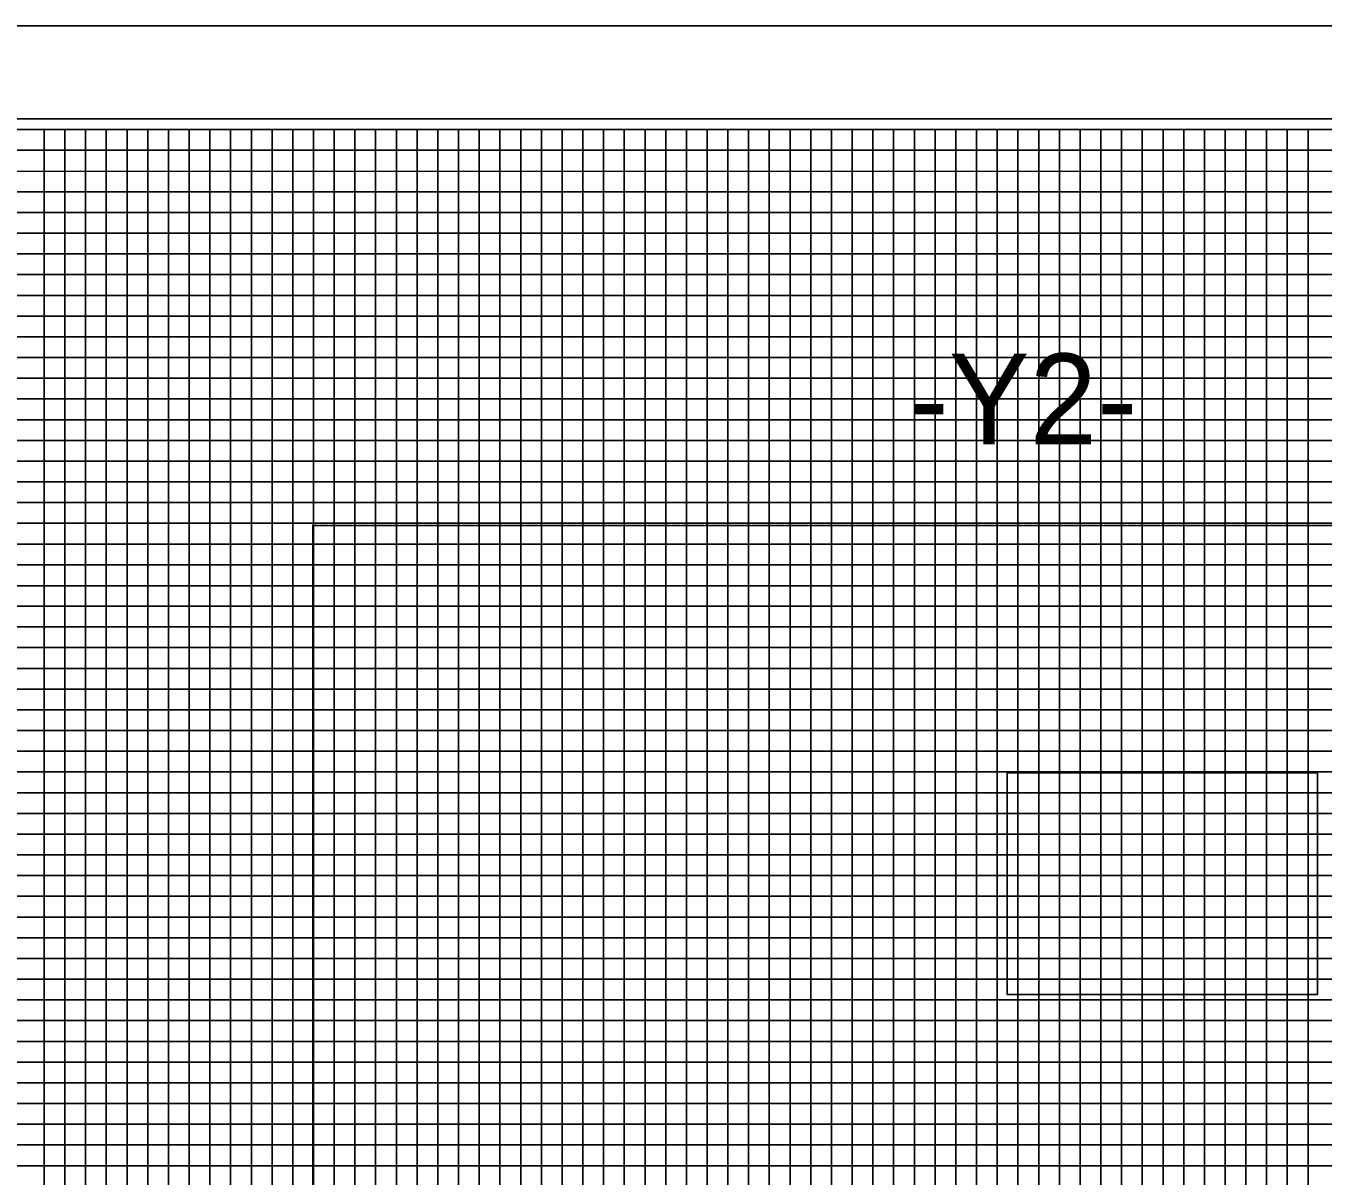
# Model space of a CAD drawing. Extents: x 1624665 to 1626605, y 896887 to 897987.
# Drawn here: x 1625613 to 1625926, y 897709.9 to 897987.4 of the extents above; entities that cross this region are included whole.
import ezdxf

# ---------------------------------------------------------------- set-up
doc = ezdxf.new("R2010")
doc.units = 0
for name, color, linetype in [('Prop DSN Text', 7, 'Continuous'), ('Prop PHM Black Shape', 7, 'Continuous'), ('Scratch_Level_1', 7, 'Continuous'), ('Sheet Cutting Line CELL', 7, 'Continuous'), ('Sheet DOT Grid CELL', 7, 'Continuous'), ('Sheet Plot Border Inside CELL', 7, 'Continuous'), ('Sheet Plot Border Outside CELL', 7, 'Continuous'), ('Sheet Profile CELL', 7, 'Continuous'), ('Sheet Profile Grid Major CELL', 7, 'Continuous'), ('Sheet Profile Grid Middle CELL', 7, 'Continuous'), ('Sheet Profile Grid Minor CELL', 7, 'Continuous')]:
    doc.layers.add(name, color=color, linetype=linetype)

msp = doc.modelspace()

# ---------------------------------------------------------------- linework, layer by layer
at = {"layer": 'Prop DSN Text'}
msp.add_lwpolyline([(1625822.4, 897912.44), (1625892.4, 897912.44), (1625892.4, 897882.44), (1625822.4, 897882.44)], close=True, dxfattribs=at)
at = {"layer": 'Prop PHM Black Shape'}
for points in [[(1625822.4, 897912.44), (1625892.4, 897912.44), (1625892.4, 897882.44), (1625822.4, 897882.44)], [(1625849.79, 897807.23), (1625924.65, 897807.23), (1625924.65, 897753.77), (1625849.79, 897753.77)]]:
    msp.add_lwpolyline(points, close=True, dxfattribs=at)
at = {"layer": 'Scratch_Level_1'}
msp.add_lwpolyline([(1625682.2, 897612.11), (1626015.27, 897612.11), (1626015.27, 897866.93), (1625682.2, 897866.93)], close=True, dxfattribs=at)
at = {"layer": 'Sheet Cutting Line CELL'}
msp.add_line((1626349.4, 897987.44), (1624665.4, 897987.44), dxfattribs=at)
at = {"layer": 'Sheet DOT Grid CELL'}
for p, q in [((1625632.4, 897462.44), (1625632.4, 897962.44)), ((1625682.4, 897462.44), (1625682.4, 897962.44)), ((1625732.4, 897462.44), (1625732.4, 897962.44)), ((1625782.4, 897462.44), (1625782.4, 897962.44)), ((1625832.4, 897462.44), (1625832.4, 897962.44)), ((1625882.4, 897462.44), (1625882.4, 897962.44)), ((1626132.35, 897912.44), (1624832.4, 897912.44)), ((1626132.35, 897862.44), (1624832.4, 897862.44)), ((1626132.4, 897812.44), (1624832.4, 897812.44)), ((1626332.4, 897762.44), (1624832.4, 897762.44)), ((1626332.4, 897712.44), (1624832.4, 897712.44))]:
    msp.add_line(p, q, dxfattribs=at)
at = {"layer": 'Sheet Plot Border Inside CELL'}
msp.add_lwpolyline([(1624678.4, 896909.89), (1626344.9, 896909.89), (1626344.9, 897964.99), (1624678.4, 897964.99)], close=True, dxfattribs=at)
at = {"layer": 'Sheet Plot Border Outside CELL'}
msp.add_lwpolyline([(1624665.4, 896887.44), (1626349.4, 896887.44), (1626349.4, 897987.44), (1624665.4, 897987.44)], close=True, dxfattribs=at)
at = {"layer": 'Sheet Profile CELL'}
msp.add_lwpolyline([(1626332.4, 897962.44), (1624832.4, 897962.44), (1624832.4, 896912.44), (1626332.4, 896912.44)], close=True, dxfattribs=at)
at = {"layer": 'Sheet Profile Grid Major CELL'}
for points in [[(1625582.4, 897462.44), (1625632.4, 897462.44), (1625632.4, 897962.44), (1625682.4, 897962.44), (1625682.4, 897462.44), (1625732.4, 897462.44), (1625732.4, 897962.44), (1625782.4, 897962.44), (1625782.4, 897462.44), (1625832.4, 897462.44), (1625832.4, 897962.44), (1625882.4, 897962.44), (1625882.4, 897462.44), (1625932.4, 897462.44), (1625932.4, 897962.44), (1625982.4, 897962.44), (1625982.4, 897462.44), (1626032.4, 897462.44), (1626032.4, 897962.44), (1626082.4, 897962.44), (1626082.4, 897462.44), (1626132.4, 897462.44), (1626132.4, 897962.44), (1626158.7, 897962.44)], [(1624832.4, 897912.44), (1626132.4, 897912.44)], [(1626132.4, 897862.44), (1624832.4, 897862.44), (1624832.4, 897812.44), (1626132.4, 897812.44)], [(1626332.4, 897762.44), (1624832.4, 897762.44), (1624832.4, 897712.44), (1626332.4, 897712.44)]]:
    msp.add_lwpolyline(points, dxfattribs=at)
at = {"layer": 'Sheet Profile Grid Middle CELL'}
msp.add_line((1624832.4, 897937.44), (1626132.35, 897937.44), dxfattribs=at)
for points in [[(1625607.4, 897462.44), (1625657.4, 897462.44), (1625657.4, 897962.44), (1625707.4, 897962.44), (1625707.4, 897462.44), (1625757.4, 897462.44), (1625757.4, 897962.44), (1625807.4, 897962.44), (1625807.4, 897462.44), (1625857.4, 897462.44), (1625857.4, 897962.44), (1625907.4, 897962.44), (1625907.4, 897462.44), (1625957.4, 897462.44), (1625957.4, 897962.44), (1626007.4, 897962.44), (1626007.4, 897462.44), (1626057.4, 897462.44), (1626057.4, 897962.44), (1626107.4, 897962.44), (1626107.4, 897462.44), (1626157.4, 897462.44), (1626157.4, 897801.39)], [(1626132.4, 897887.44), (1624832.4, 897887.44), (1624832.4, 897837.44), (1626132.4, 897837.44)], [(1626332.4, 897787.44), (1624832.4, 897787.44), (1624832.4, 897737.44), (1626157.4, 897737.44)]]:
    msp.add_lwpolyline(points, dxfattribs=at)
at = {"layer": 'Sheet Profile Grid Minor CELL'}
for p, q in [((1624882.4, 897957.44), (1626132.4, 897957.44)), ((1626132.4, 897952.44), (1624882.4, 897952.09)), ((1624882.4, 897947.44), (1626132.4, 897947.44)), ((1626132.35, 897827.44), (1624882.4, 897827.44)), ((1626132.4, 897822.44), (1624882.4, 897822.44)), ((1626132.4, 897817.44), (1624882.4, 897817.44)), ((1624882.4, 897807.44), (1626132.4, 897807.44)), ((1626132.4, 897802.44), (1624882.4, 897802.44)), ((1624882.4, 897797.44), (1626282.4, 897797.44)), ((1626282.4, 897777.44), (1624882.4, 897777.44)), ((1624882.4, 897772.44), (1626282.4, 897772.44)), ((1626282.4, 897752.44), (1624882.4, 897752.44)), ((1624882.4, 897747.44), (1626282.4, 897747.44)), ((1626282.4, 897727.44), (1624882.4, 897727.44)), ((1624882.4, 897722.44), (1626282.4, 897722.44)), ((1626282.4, 897717.44), (1624882.4, 897717.44))]:
    msp.add_line(p, q, dxfattribs=at)
for points in [[(1625617.4, 897462.44), (1625617.4, 897962.44), (1625622.4, 897962.44), (1625622.4, 897462.44)], [(1625627.4, 897462.44), (1625627.4, 897962.44), (1625637.4, 897962.44), (1625637.4, 897462.44)], [(1625642.4, 897462.44), (1625642.4, 897962.44), (1625647.4, 897962.44), (1625647.4, 897462.44)], [(1625652.4, 897462.44), (1625652.4, 897962.44), (1625662.4, 897962.44), (1625662.4, 897462.44)], [(1625667.4, 897462.44), (1625667.4, 897962.44), (1625672.4, 897962.44), (1625672.4, 897462.44)], [(1625677.4, 897462.44), (1625677.4, 897962.44), (1625687.4, 897962.44), (1625687.4, 897462.44)], [(1625692.4, 897462.44), (1625692.4, 897962.44), (1625697.4, 897962.44), (1625697.4, 897462.44)], [(1625702.4, 897462.44), (1625702.4, 897962.44), (1625712.4, 897962.44), (1625712.4, 897462.44)], [(1625717.4, 897462.44), (1625717.4, 897962.44), (1625722.4, 897962.44), (1625722.4, 897462.44)], [(1625727.4, 897462.44), (1625727.4, 897962.44), (1625737.4, 897962.44), (1625737.4, 897462.44)], [(1625742.4, 897462.44), (1625742.4, 897962.44), (1625747.4, 897962.44), (1625747.4, 897462.44)], [(1625752.4, 897462.44), (1625752.4, 897962.44), (1625762.4, 897962.44), (1625762.4, 897462.44)], [(1625767.4, 897462.44), (1625767.4, 897962.44), (1625772.4, 897962.44), (1625772.4, 897462.44)], [(1625777.4, 897462.44), (1625777.4, 897962.44), (1625787.4, 897962.44), (1625787.4, 897462.44)], [(1625792.4, 897462.44), (1625792.4, 897962.44), (1625797.4, 897962.44), (1625797.4, 897462.44)], [(1625802.4, 897462.44), (1625802.4, 897962.44), (1625812.4, 897962.44), (1625812.4, 897462.44)], [(1625817.4, 897462.44), (1625817.4, 897962.44), (1625822.4, 897962.44), (1625822.4, 897462.44)], [(1625827.4, 897462.44), (1625827.4, 897962.44), (1625837.4, 897962.44), (1625837.4, 897462.44)], [(1625842.4, 897462.44), (1625842.4, 897962.44), (1625847.4, 897962.44), (1625847.4, 897462.44)], [(1625852.4, 897462.44), (1625852.4, 897962.44), (1625862.4, 897962.44), (1625862.4, 897462.44)], [(1625867.4, 897462.44), (1625867.4, 897962.44), (1625872.4, 897962.44), (1625872.4, 897462.44)], [(1625877.4, 897462.44), (1625877.4, 897962.44), (1625887.4, 897962.44), (1625887.4, 897462.44)], [(1625892.4, 897462.44), (1625892.4, 897962.44), (1625897.4, 897962.44), (1625897.4, 897462.44)], [(1625902.4, 897462.44), (1625902.4, 897962.44), (1625912.4, 897962.44), (1625912.4, 897462.44)], [(1625917.4, 897462.44), (1625917.4, 897962.44), (1625922.4, 897962.44), (1625922.4, 897462.44)], [(1626132.4, 897942.44), (1624882.4, 897942.44), (1624882.4, 897932.44), (1626132.4, 897932.44)], [(1626132.35, 897927.44), (1624882.4, 897927.44), (1624882.4, 897922.44), (1626132.4, 897922.44)], [(1626132.4, 897917.44), (1624882.4, 897917.44), (1624882.4, 897907.44), (1626132.4, 897907.44)], [(1626132.4, 897902.44), (1624882.4, 897902.44), (1624882.4, 897897.44), (1626132.4, 897897.44)], [(1626132.4, 897892.44), (1624882.4, 897892.44), (1624882.4, 897882.44), (1626132.4, 897882.44)], [(1626132.4, 897877.44), (1624882.4, 897877.44), (1624882.4, 897872.44), (1626132.4, 897872.44)], [(1626132.4, 897867.44), (1624882.4, 897867.44), (1624882.4, 897857.44), (1626132.4, 897857.44)], [(1626132.4, 897852.34), (1624882.5, 897852.34), (1624882.5, 897847.44), (1626132.4, 897847.44)], [(1626132.4, 897842.44), (1624882.4, 897842.44), (1624882.4, 897832.44), (1626132.4, 897832.44)], [(1626282.4, 897792.44), (1624882.4, 897792.44), (1624882.4, 897782.44), (1626282.4, 897782.44)], [(1626282.4, 897767.44), (1624882.4, 897767.44), (1624882.4, 897757.44), (1626282.4, 897757.44)], [(1626282.4, 897742.44), (1624882.4, 897742.44), (1624882.4, 897732.44), (1626282.4, 897732.44)]]:
    msp.add_lwpolyline(points, dxfattribs=at)

# ---------------------------------------------------------------- texts
at = {"layer": 'Prop DSN Text'}
msp.add_text('-Y2-', height=21.875, dxfattribs=at).set_placement((1625825.95, 897886.5))

doc.saveas('drawing.dxf')
